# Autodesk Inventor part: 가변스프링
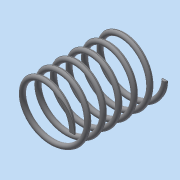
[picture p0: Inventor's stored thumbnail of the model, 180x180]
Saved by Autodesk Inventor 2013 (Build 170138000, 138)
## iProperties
Created: 2018-06
Part Number: 가변스프링
Material: 강철, 연강
Document SubType Name: Modeling
Designer: Administrator
Density: 7.86 g/cm^3
Mass: 82.8071 g
Surface Area: 106.473 cm^2
Volume: 10.5353 cm^3
Author: Administrator
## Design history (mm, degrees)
sketch "스케치1"
  geometry: L1 (0, 0)-(0, 73.25); L2 (0, 73.25)-(22.5, 73.25); L3 (0, 0)-(22.5, 0); C1 r 2 at (22.5, 0)
  constraints: 6 end point, 1 centre point, 1 coincident, 1 parallel, 1 perpendicular, 1 vertical
  dimensions: "d0" = 73.25 distance of L1.start L1.end (derived); "d1" = 22.5 distance of L1.end L2.end; "d2" = 22.5 distance of L1.start L3.end; "d3" = 4 diameter of C1
feature "코일1" sketch "스케치1" pitch "d4" = 10; turns "d6" = 6; dims "d5" = 73.25 (= d0), "d7" = 0, angle "d8" = 90 deg, angle "d9" = 90 deg, "d10" = 0, "d11" = 0
sketch "스케치2"
  geometry: L1 (73.25, 25)-(0, 25); L2 (0, 25)-(0, -25); L3 (0, -25)-(73.25, -25); L4 (73.25, -25)-(73.25, 25); 2 further points
  constraints: 8 end point, 2 parallel, 1 coincident, 1 horizontal, 1 midpoint, 1 perpendicular
  dimensions: "d12" = 50 distance of L3.end L1.start; "d14" = 73.25 distance of L2.end L3.end (derived)
extrude "돌출1" sketch "스케치2" stored distance "d15" = 10; taper "d16" = 0 deg
node "솔리드1"
